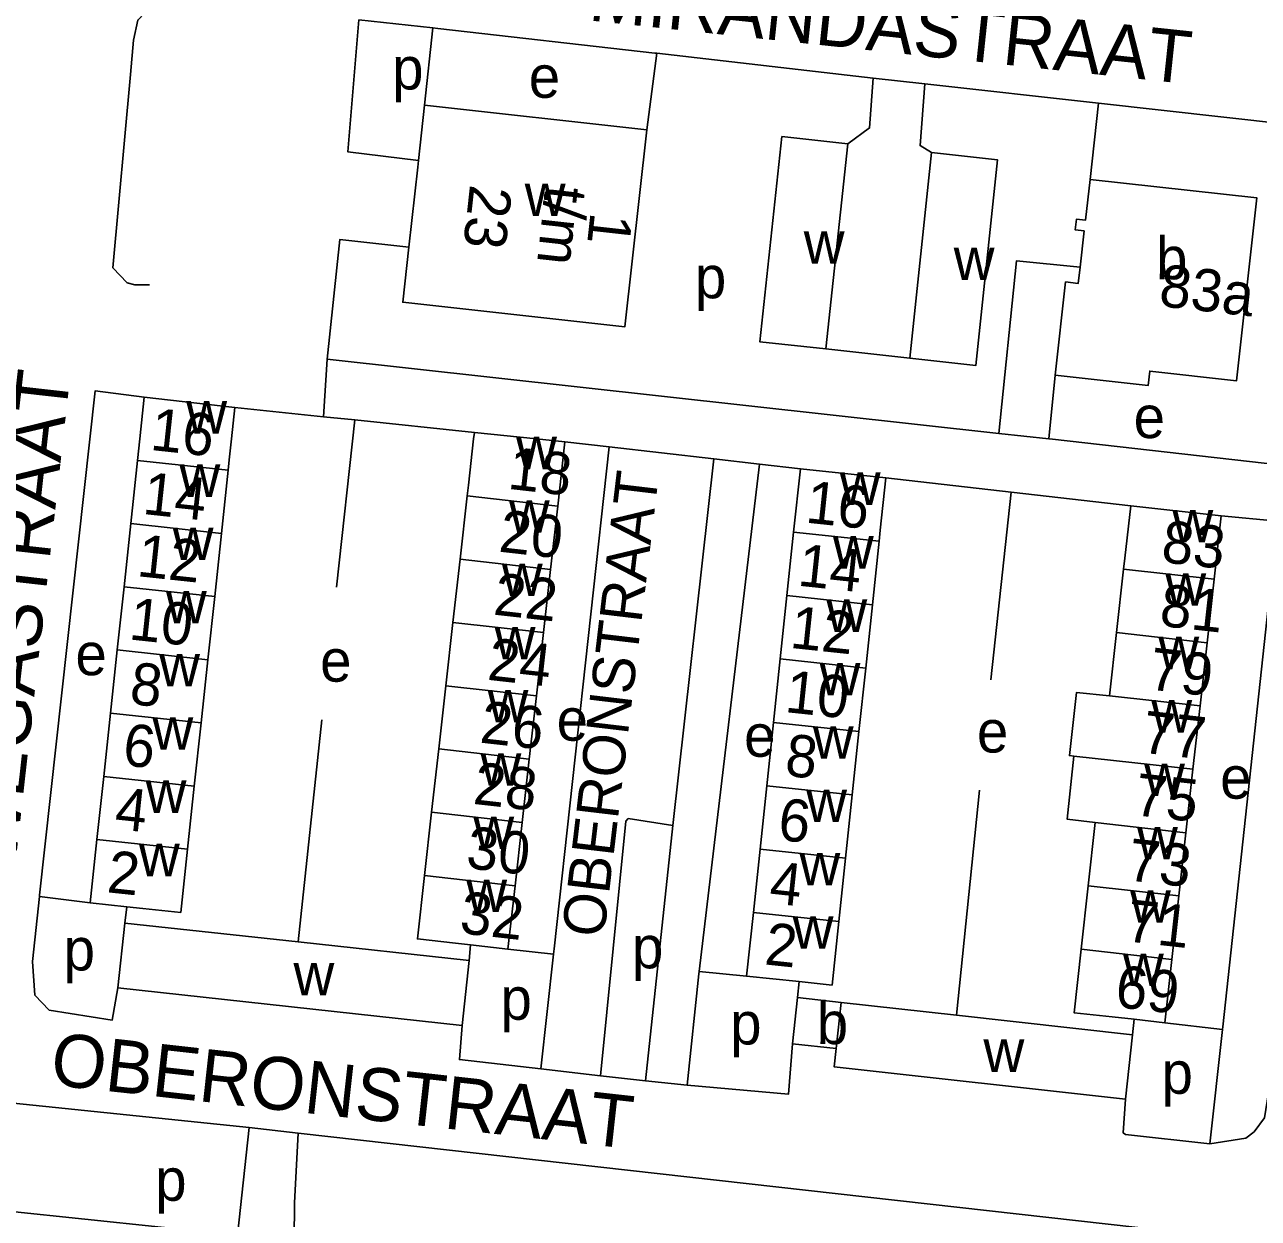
# Model space of a CAD drawing. Extents: x 161936 to 163647, y 386450 to 388633.
# Drawn here: x 162171.1 to 162287.9, y 386926.2 to 387039.2 of the extents above; entities that cross this region are included whole.
import ezdxf

# ---------------------------------------------------------------- set-up
doc = ezdxf.new("R2010")
doc.units = 0
for name, color, linetype in [('BLT_Basislijn', 7, 'Continuous'), ('BLT_Bebouwing', 7, 'Continuous'), ('BLT_Centroide', 7, 'Continuous'), ('BLT_Huisnummer', 7, 'Continuous'), ('BLT_Huisnummer_ tussenligend', 7, 'Continuous'), ('BLT_Huisnummer_reeks', 7, 'Continuous'), ('BLT_Onderverdeling_panden', 7, 'Continuous'), ('BLT_Straatnaam', 7, 'Continuous'), ('BLT_Straatnaam_verkleind', 7, 'Continuous')]:
    doc.layers.add(name, color=color, linetype=linetype)

msp = doc.modelspace()

# ---------------------------------------------------------------- linework, layer by layer
at = {"layer": 'BLT_Basislijn'}
for p, q in [((162202.74, 387039.68), (162209.75, 387038.9)), ((162208.94, 387031.59), (162209.75, 387038.9)), ((162229.99, 387029.27), (162230.94, 387036.51)), ((162230.94, 387036.51), (162251.42, 387034.15)), ((162251.42, 387034.15), (162256.34, 387033.6)), ((162256.34, 387033.6), (162272.78, 387031.77)), ((162271.98, 387024.57), (162272.78, 387031.77)), ((162272.78, 387031.77), (162293.82, 387029.42)), ((162254.92, 387007.63), (162246.94, 387008.51)), ((162199.74, 387007.53), (162199.37, 387002.1)), ((162263.32, 387000.52), (162199.74, 387007.53)), ((162268.66, 387006.03), (162268.07, 387000.01)), ((162199.37, 387002.1), (162190.99, 387002.98)), ((162202.35, 387001.79), (162199.37, 387002.1)), ((162200.6, 386985.96), (162202.35, 387001.79)), ((162213.67, 387000.59), (162202.35, 387001.79)), ((162222.25, 386999.73), (162226.42, 386999.25)), ((162268.07, 387000.01), (162263.32, 387000.52)), ((162226.42, 386999.25), (162236.35, 386998.11)), ((162236.35, 386998.11), (162232.45, 386963.4)), ((162240.67, 386997.61), (162234.96, 386949.56)), ((162236.35, 386998.11), (162240.67, 386997.61)), ((162240.67, 386997.61), (162244.54, 386997.17)), ((162252.63, 386996.31), (162264.51, 386994.95)), ((162262.57, 386977.19), (162264.51, 386994.95)), ((162264.51, 386994.95), (162275.82, 386993.66)), ((162199.23, 386973.39), (162196.97, 386952.38)), ((162261.49, 386966.75), (162259.34, 386945.42)), ((162232.45, 386963.4), (162229.86, 386939.22)), ((162177.29, 386956.07), (162172.48, 386956.67)), ((162180.76, 386955.7), (162180.57, 386954.16)), ((162213.17, 386950.62), (162213.31, 386952.09)), ((162216.85, 386951.69), (162221.15, 386951.21)), ((162221.15, 386951.21), (162219.95, 386940.35)), ((162239.45, 386949.14), (162234.96, 386949.56)), ((162244.27, 386947.1), (162244.42, 386948.61)), ((162276, 386943.57), (162276.15, 386945.04)), ((162279.04, 386944.72), (162284.53, 386944.09)), ((162283.32, 386933.25), (162284.53, 386944.09)), ((162219.95, 386940.35), (162225.6, 386939.7)), ((162229.86, 386939.22), (162225.6, 386939.7)), ((162233.83, 386938.8), (162229.86, 386939.22)), ((162192.34, 386934.81), (162196.99, 386934.27)), ((162196.99, 386934.27), (162282.12, 386924.71))]:
    msp.add_line(p, q, dxfattribs=at)
for points in [[(162185.66, 387041.05), (162183.02, 387040.95), (162181.79, 387039.65), (162181.4, 387037.74), (162181.09, 387034.51)], [(162202.74, 387039.68), (162201.68, 387027.18), (162208.37, 387026.36)], [(162209.75, 387038.9), (162210.2, 387038.85), (162230.77, 387036.53), (162230.94, 387036.51)], [(162181.09, 387034.51), (162179.44, 387016.2), (162180.8, 387014.78), (162181.53, 387014.59), (162182.91, 387014.59)], [(162249.02, 387027.93), (162251.09, 387029.44), (162251.42, 387034.15)], [(162256.97, 387027.11), (162255.87, 387027.77), (162256.34, 387033.6)], [(162293.82, 387029.42), (162290.12, 386997.5), (162268.42, 386999.97), (162268.07, 387000.01)], [(162293.82, 387029.42), (162295.39, 387029.14), (162297.43, 387027.42), (162298.16, 387024.3), (162298.12, 387022.89), (162289.13, 386939.66), (162288.49, 386935.72), (162287.51, 386934.38), (162286.71, 386933.79), (162283.32, 386933.25)], [(162207.46, 387018.14), (162200.92, 387018.86), (162199.74, 387007.53)], [(162271.03, 387016.26), (162265.02, 387016.87), (162263.32, 387000.52)], [(162182.41, 387003.94), (162177.75, 387004.54), (162172.49, 386956.81), (162172.48, 386956.67)], [(162226.42, 386999.25), (162221.21, 386951.73), (162221.15, 386951.21)], [(162284.39, 386992.7), (162289.73, 386992.2), (162284.56, 386944.34), (162284.53, 386944.09)], [(162232.45, 386963.4), (162228.24, 386964.06), (162228, 386963.79), (162225.6, 386939.7)], [(162172.48, 386956.67), (162171.81, 386950.5), (162172.05, 386947.32), (162173.4, 386945.92), (162179.37, 386944.97), (162179.92, 386948.02)], [(162234.96, 386949.56), (162234.94, 386949.34), (162233.83, 386938.8)], [(162212.52, 386944.45), (162212.25, 386941.23), (162219.95, 386940.35)], [(162243.79, 386942.73), (162243.42, 386937.96), (162233.83, 386938.8)], [(162192.34, 386934.81), (162170.04, 386937.09), (162169.7, 386934.82)], [(162283.32, 386933.25), (162275.34, 386934.12), (162275.11, 386934.28), (162275.32, 386937.47)], [(162192.34, 386934.81), (162191.25, 386924.61), (162169.56, 386926.87), (162169.13, 386927.4), (162169.7, 386934.82)], [(162196.99, 386934.27), (162196.63, 386927.66), (162196.6, 386924.16), (162196.89, 386924.09), (162278.74, 386914.77), (162281.01, 386914.82), (162282.12, 386924.71)]]:
    msp.add_lwpolyline(points, dxfattribs=at)
at = {"layer": 'BLT_Bebouwing'}
for p, q in [((162208.94, 387031.59), (162208.37, 387026.36)), ((162229.99, 387029.27), (162208.94, 387031.59)), ((162249.02, 387027.93), (162246.94, 387008.51)), ((162256.97, 387027.11), (162254.92, 387007.63)), ((162190.99, 387002.98), (162182.41, 387003.94)), ((162221.57, 386993.64), (162222.25, 386999.73)), ((162181.13, 386991.97), (162181.77, 386997.95)), ((162190.36, 386997.04), (162189.71, 386991.05)), ((162243.9, 386991.16), (162244.54, 386997.17)), ((162244.54, 386997.17), (162252.63, 386996.31)), ((162212.99, 386994.6), (162212.32, 386988.61)), ((162220.89, 386987.64), (162221.57, 386993.64)), ((162284.39, 386992.7), (162275.82, 386993.66)), ((162283.72, 386986.7), (162284.39, 386992.7)), ((162180.49, 386985.99), (162181.13, 386991.97)), ((162189.71, 386991.05), (162189.08, 386985.07)), ((162243.27, 386985.16), (162243.9, 386991.16)), ((162252, 386990.31), (162251.36, 386984.3)), ((162212.32, 386988.61), (162211.64, 386982.62)), ((162220.22, 386981.65), (162220.89, 386987.64)), ((162275.15, 386987.66), (162274.48, 386981.66)), ((162283.06, 386980.7), (162283.72, 386986.7)), ((162179.85, 386980.01), (162180.49, 386985.99)), ((162189.08, 386985.07), (162188.43, 386979.09)), ((162242.63, 386979.16), (162243.27, 386985.16)), ((162251.36, 386984.3), (162250.73, 386978.3)), ((162211.64, 386982.62), (162210.97, 386976.63)), ((162219.54, 386975.66), (162220.22, 386981.65)), ((162274.48, 386981.66), (162273.81, 386975.66)), ((162179.21, 386974.02), (162179.85, 386980.01)), ((162282.39, 386974.71), (162283.06, 386980.7)), ((162188.43, 386979.09), (162187.79, 386973.1)), ((162241.99, 386973.15), (162242.63, 386979.16)), ((162250.73, 386978.3), (162250.09, 386972.3)), ((162210.97, 386976.63), (162210.3, 386970.64)), ((162218.87, 386969.67), (162219.54, 386975.66)), ((162178.57, 386968.04), (162179.21, 386974.02)), ((162281.72, 386968.71), (162282.39, 386974.71)), ((162187.79, 386973.1), (162187.15, 386967.12)), ((162241.36, 386967.15), (162241.99, 386973.15)), ((162250.09, 386972.3), (162249.46, 386966.29)), ((162210.3, 386970.64), (162209.62, 386964.65)), ((162218.2, 386963.68), (162218.87, 386969.67)), ((162177.93, 386962.06), (162178.57, 386968.04)), ((162281.05, 386962.71), (162281.72, 386968.71)), ((162187.15, 386967.12), (162186.51, 386961.14)), ((162240.72, 386961.15), (162241.36, 386967.15)), ((162249.46, 386966.29), (162248.82, 386960.29)), ((162209.62, 386964.65), (162208.95, 386958.65)), ((162217.52, 386957.69), (162218.2, 386963.68)), ((162272.47, 386963.67), (162271.8, 386957.67)), ((162280.38, 386956.72), (162281.05, 386962.71)), ((162177.29, 386956.07), (162177.93, 386962.06)), ((162240.09, 386955.15), (162240.72, 386961.15)), ((162248.82, 386960.29), (162248.18, 386954.29)), ((162216.85, 386951.69), (162217.52, 386957.69)), ((162271.8, 386957.67), (162271.13, 386951.68)), ((162279.71, 386950.72), (162280.38, 386956.72)), ((162180.76, 386955.7), (162177.29, 386956.07)), ((162179.92, 386948.02), (162180.57, 386954.16)), ((162180.57, 386954.16), (162196.97, 386952.38)), ((162239.45, 386949.14), (162240.09, 386955.15)), ((162196.97, 386952.38), (162213.17, 386950.62)), ((162213.31, 386952.09), (162216.85, 386951.69)), ((162213.17, 386950.62), (162212.52, 386944.45)), ((162279.04, 386944.72), (162279.71, 386950.72)), ((162244.42, 386948.61), (162239.45, 386949.14)), ((162212.52, 386944.45), (162179.92, 386948.02)), ((162244.27, 386947.1), (162243.79, 386942.73)), ((162248.4, 386946.64), (162244.27, 386947.1)), ((162259.34, 386945.42), (162248.4, 386946.64)), ((162276, 386943.57), (162259.34, 386945.42)), ((162276.15, 386945.04), (162279.04, 386944.72)), ((162275.32, 386937.47), (162276, 386943.57)), ((162243.79, 386942.73), (162247.94, 386942.27))]:
    msp.add_line(p, q, dxfattribs=at)
for points in [[(162207.46, 387018.14), (162206.89, 387012.93), (162227.93, 387010.61), (162229.99, 387029.27)], [(162246.94, 387008.51), (162240.7, 387009.2), (162242.79, 387028.62), (162249.02, 387027.93)], [(162254.92, 387007.63), (162261.15, 387006.94), (162263.2, 387026.42), (162256.97, 387027.11)], [(162208.37, 387026.36), (162208.3, 387025.71), (162207.46, 387018.14)], [(162268.66, 387006.03), (162277.47, 387005.05), (162277.62, 387006.42), (162285.85, 387005.5), (162287.78, 387022.81), (162271.98, 387024.57)], [(162271.98, 387024.57), (162271.55, 387020.71), (162270.69, 387020.81), (162270.57, 387019.78), (162271.41, 387019.68), (162271.03, 387016.26)], [(162271.03, 387016.26), (162270.86, 387014.72), (162269.65, 387014.86), (162268.66, 387006.03)], [(162181.77, 386997.95), (162181.99, 387000), (162182.41, 387003.94)], [(162190.99, 387002.98), (162190.67, 387000), (162190.46, 386998.01), (162190.36, 386997.04)], [(162213.67, 387000.59), (162213.6, 387000), (162213.11, 386995.62), (162212.99, 386994.6)], [(162222.25, 386999.73), (162219.55, 387000), (162213.67, 387000.59)], [(162252.63, 386996.31), (162252.11, 386991.34), (162252, 386990.31)], [(162275.82, 386993.66), (162275.26, 386988.69), (162275.15, 386987.66)], [(162273.81, 386975.66), (162270.68, 386975.98), (162270.02, 386970.01), (162270.45, 386969.96)], [(162270.45, 386969.96), (162269.79, 386964), (162272.47, 386963.67)], [(162186.51, 386961.14), (162185.87, 386955.16), (162182.26, 386955.54), (162180.76, 386955.7)], [(162208.95, 386958.65), (162208.27, 386952.66), (162211.88, 386952.25), (162213.31, 386952.09)], [(162248.18, 386954.29), (162247.55, 386948.28), (162244.42, 386948.61)], [(162271.13, 386951.68), (162270.46, 386945.67), (162274.07, 386945.27), (162276.15, 386945.04)], [(162247.94, 386942.27), (162247.75, 386940.53), (162275.32, 386937.47)]]:
    msp.add_lwpolyline(points, dxfattribs=at)
at = {"layer": 'BLT_Onderverdeling_panden'}
for p, q in [((162181.77, 386997.95), (162190.36, 386997.04)), ((162212.99, 386994.6), (162221.57, 386993.64)), ((162181.13, 386991.97), (162189.71, 386991.05)), ((162243.9, 386991.16), (162252, 386990.31)), ((162212.32, 386988.61), (162220.89, 386987.64)), ((162275.15, 386987.66), (162283.72, 386986.7)), ((162180.49, 386985.99), (162189.08, 386985.07)), ((162243.27, 386985.16), (162251.36, 386984.3)), ((162211.64, 386982.62), (162220.22, 386981.65)), ((162274.48, 386981.66), (162283.06, 386980.7)), ((162179.85, 386980.01), (162188.43, 386979.09)), ((162242.63, 386979.16), (162250.73, 386978.3)), ((162210.97, 386976.63), (162219.54, 386975.66)), ((162273.81, 386975.66), (162282.39, 386974.71)), ((162179.21, 386974.02), (162187.79, 386973.1)), ((162241.99, 386973.15), (162250.09, 386972.3)), ((162210.3, 386970.64), (162218.87, 386969.67)), ((162270.45, 386969.96), (162281.72, 386968.71)), ((162178.57, 386968.04), (162187.15, 386967.12)), ((162241.36, 386967.15), (162249.46, 386966.29)), ((162209.62, 386964.65), (162218.2, 386963.68)), ((162272.47, 386963.67), (162281.05, 386962.71)), ((162177.93, 386962.06), (162186.51, 386961.14)), ((162240.72, 386961.15), (162248.82, 386960.29)), ((162208.95, 386958.65), (162217.52, 386957.69)), ((162271.8, 386957.67), (162280.38, 386956.72)), ((162240.09, 386955.15), (162248.18, 386954.29)), ((162271.13, 386951.68), (162279.71, 386950.72)), ((162247.94, 386942.27), (162248.4, 386946.64))]:
    msp.add_line(p, q, dxfattribs=at)

# ---------------------------------------------------------------- texts
at = {"layer": 'BLT_Centroide'}
for s, p in [('p', (162205.88, 387033.08)), ('e', (162218.82, 387032.29)), ('w', (162218.44, 387021.09)), ('w', (162244.86, 387016.58)), ('b', (162278.22, 387015.11)), ('w', (162259.06, 387015.03)), ('p', (162234.55, 387013.31)), ('w', (162186.38, 387000.5)), ('e', (162276.1, 387000.07)), ('w', (162217.62, 386997.12)), ('w', (162185.74, 386994.5)), ('w', (162248.27, 386993.75)), ('w', (162216.94, 386991.12)), ('w', (162279.77, 386990.19)), ('w', (162185.1, 386988.53)), ('w', (162247.62, 386987.72)), ('w', (162216.27, 386985.12)), ('w', (162279.1, 386984.19)), ('w', (162184.46, 386982.53)), ('w', (162247, 386981.72)), ('w', (162215.59, 386979.12)), ('w', (162278.44, 386978.19)), ('e', (162175.89, 386977.62)), ('e', (162199.06, 386977.01)), ('w', (162183.82, 386976.56)), ('w', (162246.36, 386975.72)), ('w', (162214.92, 386973.16)), ('w', (162277.77, 386972.19)), ('e', (162221.46, 386971.42)), ('w', (162183.18, 386970.56)), ('e', (162239.21, 386969.9)), ('w', (162245.72, 386969.72)), ('e', (162261.26, 386970.3)), ('w', (162214.25, 386967.16)), ('w', (162277.09, 386966.19)), ('e', (162284.29, 386965.93)), ('w', (162182.54, 386964.59)), ('w', (162245.09, 386963.72)), ('w', (162213.57, 386961.16)), ('w', (162276.42, 386960.19)), ('w', (162181.9, 386958.59)), ('w', (162244.45, 386957.72)), ('w', (162212.9, 386955.19)), ('w', (162275.76, 386954.19)), ('w', (162243.81, 386951.72)), ('p', (162228.59, 386949.87)), ('p', (162174.77, 386949.67)), ('w', (162275.09, 386948.19)), ('w', (162196.54, 386947.31)), ('p', (162216.14, 386945)), ('b', (162246.09, 386942.69)), ('p', (162237.89, 386942.66)), ('w', (162261.88, 386940.06)), ('p', (162278.74, 386937.99)), ('p', (162183.44, 386927.86))]:
    msp.add_text(s, height=4, dxfattribs=at).set_placement(p)
at = {"layer": 'BLT_Huisnummer'}
for s, rotation, p in [('83a', 353.6239, (162278.4, 387012.58)), ('16', 353.8871, (162182.89, 386998.96)), ('18', 353.5792, (162216.74, 386995.28)), ('16', 353.956, (162244.94, 386992.08)), ('83', 353.6327, (162278.62, 386988.34)), ('22', 353.5792, (162215.38, 386983.37)), ('10', 353.8864, (162180.87, 386981.02)), ('10', 353.9553, (162242.99, 386974.14)), ('26', 353.5792, (162214.1, 386971.25)), ('77', 353.6327, (162276.78, 386970.3)), ('6', 353.8923, (162180.27, 386969.11)), ('6', 353.9545, (162242.32, 386962.04)), ('2', 353.9142, (162178.79, 386957.08)), ('73', 353.6327, (162275.41, 386958.21)), ('32', 353.5784, (162212.18, 386953.21)), ('2', 353.9508, (162241.06, 386950.25)), ('69', 353.6249, (162274.25, 386946.22))]:
    msp.add_text(s, height=4, rotation=rotation, dxfattribs=at).set_placement(p)
at = {"layer": 'BLT_Huisnummer_ tussenligend'}
for s, rotation, p in [('14', 353.8864, (162182.17, 386992.9)), ('20', 353.5792, (162215.89, 386989.33)), ('12', 353.8864, (162181.63, 386987.01)), ('14', 353.9553, (162244.2, 386986.11)), ('81', 353.6327, (162278.46, 386982.31)), ('12', 353.9553, (162243.47, 386980.22)), ('24', 353.5792, (162214.81, 386977.2)), ('79', 353.6327, (162277.45, 386976.28)), ('8', 353.8923, (162180.93, 386974.91)), ('8', 353.9545, (162242.98, 386968.12)), ('28', 353.5792, (162213.46, 386965.45)), ('75', 353.6327, (162276.06, 386964.38)), ('4', 353.9142, (162179.52, 386963.07)), ('30', 353.5792, (162212.79, 386959.37)), ('4', 353.9508, (162241.51, 386956.05)), ('71', 353.6249, (162275.27, 386952.44))]:
    msp.add_text(s, height=4, rotation=rotation, dxfattribs=at).set_placement(p)
at = {"layer": 'BLT_Huisnummer_reeks'}
for s, rotation, p in [('23', 263.7041, (162213.27, 387024.15)), ('t/m', 263.7063, (162220.42, 387024.07)), ('1', 263.7063, (162224.68, 387021.53))]:
    msp.add_text(s, height=4, rotation=rotation, dxfattribs=at).set_placement(p)
at = {"layer": 'BLT_Straatnaam'}
for s, height, rotation, p in [('MIRANDASTRAAT', 5, 353.9308, (162224.4, 387039.63)), ('WEGASTRAAT', 5, 83.5874, (162170.2, 386959.66)), ('OBERONSTRAAT', 4.9999, 353.6852, (162173.4, 386938.86))]:
    msp.add_text(s, height=height, rotation=rotation, dxfattribs=at).set_placement(p)
at = {"layer": 'BLT_Straatnaam_verkleind'}
msp.add_text('OBERONSTRAAT', height=3.9999, rotation=83.2143, dxfattribs=at).set_placement((162225.92, 386952.69))

doc.saveas('drawing.dxf')
